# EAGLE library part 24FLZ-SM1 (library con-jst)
CONNECTOR
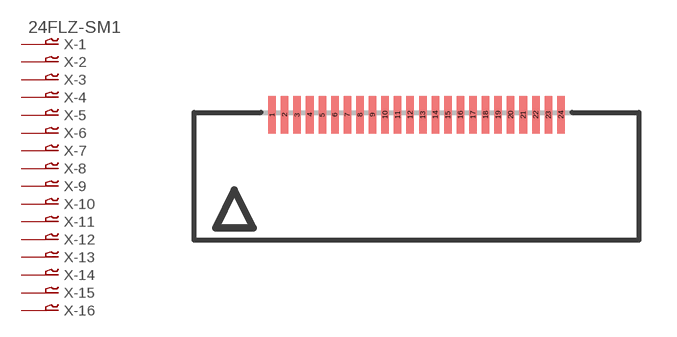
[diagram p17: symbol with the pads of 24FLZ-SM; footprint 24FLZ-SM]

Designator prefix X; gates -1=P-VN -2=P-N -3=P-N -4=P-N -5=P-N -6=P-N -7=P-N -8=P-N -9=P-N -10=P-N -11=P-N -12=P-N -13=P-N -14=P-N -15=P-N -16=P-N -17=P-N -18=P-N -19=P-N -20=P-N -21=P-N -22=P-N -23=P-N -24=P-N

## 24FLZ-SM1 (OC_FARNELL: unknown; OC_NEWARK: unknown)  [24FLZ-SM]
1  -1:1  pas
2  -2:1  pas
3  -3:1  pas
4  -4:1  pas
5  -5:1  pas
6  -6:1  pas
7  -7:1  pas
8  -8:1  pas
9  -9:1  pas
10  -10:1  pas
11  -11:1  pas
12  -12:1  pas
13  -13:1  pas
14  -14:1  pas
15  -15:1  pas
16  -16:1  pas
17  -17:1  pas
18  -18:1  pas
19  -19:1  pas
20  -20:1  pas
21  -21:1  pas
22  -22:1  pas
23  -23:1  pas
24  -24:1  pas

## Footprint 24FLZ-SM (pad centres in mm)
CONNECTOR
smd 0.3 x 1.5: 1 -5.75,2.5; 2 -5.25,2.5; 3 -4.75,2.5; 4 -4.25,2.5; 5 -3.75,2.5; 6 -3.25,2.5; 7 -2.75,2.5; 8 -2.25,2.5; 9 -1.75,2.5; 10 -1.25,2.5; 11 -0.75,2.5; 12 -0.25,2.5; 13 0.25,2.5; 14 0.75,2.5; 15 1.25,2.5; 16 1.75,2.5; 17 2.25,2.5; 18 2.75,2.5; 19 3.25,2.5; 20 3.75,2.5; 21 4.25,2.5; 22 4.75,2.5; 23 5.25,2.5; 24 5.75,2.5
